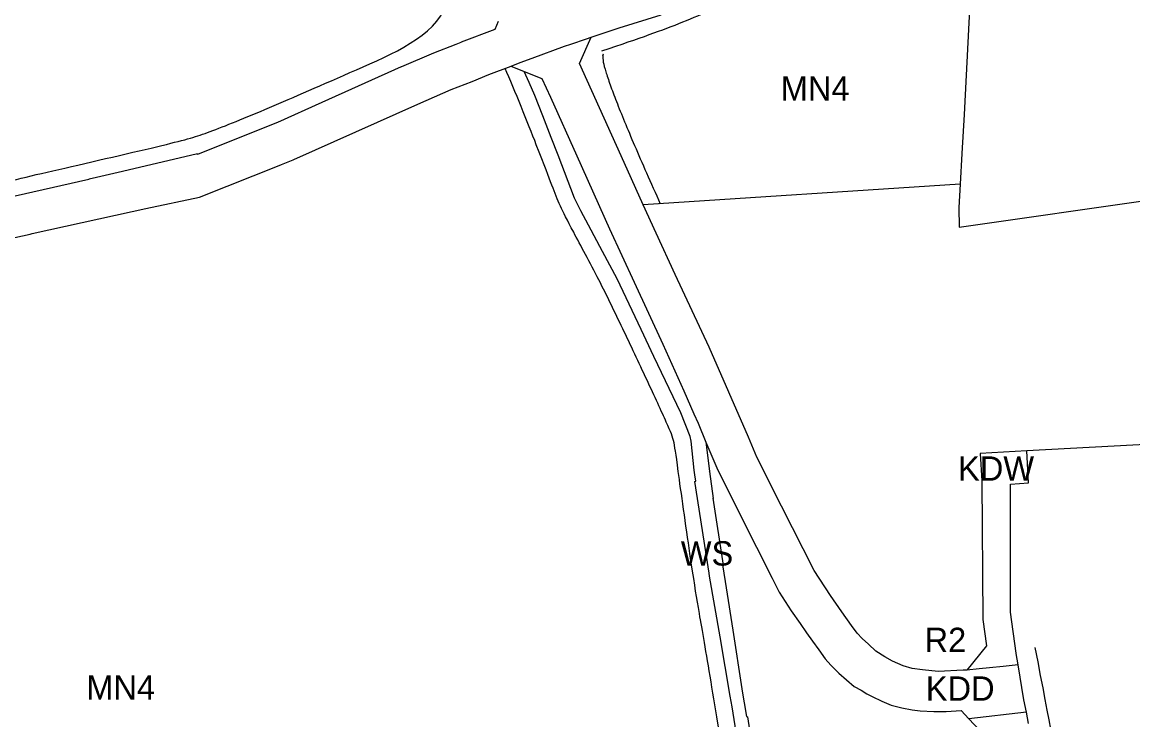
# Model space of a CAD drawing. Extents: x 7413438 to 7416393, y 5541665 to 5544118.
# Drawn here: x 7415261.6 to 7415535.1, y 5542643.7 to 5542815.6 of the extents above; entities that cross this region are included whole.
import ezdxf

# ---------------------------------------------------------------- set-up
doc = ezdxf.new("R2010")
doc.units = 0
for name, color, linetype in [('linie_rozgraniczajace', 7, 'Continuous'), ('linie_zabudowy_nieprzekraczalne', 7, 'Continuous'), ('oznaczenia_przeznaczen', 7, 'Continuous')]:
    doc.layers.add(name, color=color, linetype=linetype)

msp = doc.modelspace()

# ---------------------------------------------------------------- linework, layer by layer
at = {"layer": 'linie_rozgraniczajace'}
for p, q in [((7415495.27, 5542825.28), (7415494.71, 5542815.37)), ((7415378.77, 5542815.75), (7415377.96, 5542813.77)), ((7415408.58, 5542814.17), (7415418.95, 5542817.4)), ((7415494.71, 5542815.37), (7415493.57, 5542792.82)), ((7415377.96, 5542813.77), (7415369.66, 5542810.61)), ((7415402.47, 5542812.13), (7415407.64, 5542813.88)), ((7415407.64, 5542813.88), (7415408.58, 5542814.17)), ((7415368.34, 5542810.08), (7415362.89, 5542807.96)), ((7415369.65, 5542810.59), (7415368.34, 5542810.08)), ((7415369.66, 5542810.61), (7415369.65, 5542810.59)), ((7415395.17, 5542809.66), (7415396.67, 5542810.17)), ((7415396.67, 5542810.17), (7415400.56, 5542811.49)), ((7415398.83, 5542805.37), (7415401.7, 5542811.87)), ((7415400.56, 5542811.49), (7415401.7, 5542811.87)), ((7415401.7, 5542811.87), (7415402.47, 5542812.13)), ((7415362.89, 5542807.96), (7415355.01, 5542804.56)), ((7415387.22, 5542806.71), (7415395.17, 5542809.66)), ((7415354.95, 5542804.53), (7415335.37, 5542795.76)), ((7415355.01, 5542804.56), (7415354.95, 5542804.53)), ((7415376.48, 5542802.71), (7415382, 5542804.76)), ((7415382, 5542804.76), (7415384.26, 5542805.6)), ((7415382, 5542804.76), (7415382.15, 5542804.68)), ((7415382.15, 5542804.68), (7415385.21, 5542803.45)), ((7415384.26, 5542805.6), (7415387.22, 5542806.71)), ((7415409.81, 5542780.98), (7415398.83, 5542805.37)), ((7415372.42, 5542800.93), (7415376.48, 5542802.71)), ((7415386.41, 5542800.74), (7415385.21, 5542803.45)), ((7415385.21, 5542803.45), (7415389.54, 5542801.72)), ((7415389.54, 5542801.72), (7415391.71, 5542797.07)), ((7415359.01, 5542795.39), (7415367.27, 5542798.96)), ((7415367.27, 5542798.96), (7415372.42, 5542800.93)), ((7415387.86, 5542797.46), (7415386.41, 5542800.74)), ((7415389.79, 5542792.48), (7415387.86, 5542797.46)), ((7415391.71, 5542797.07), (7415398.18, 5542782.61)), ((7415335.37, 5542795.76), (7415324.48, 5542790.88)), ((7415328.48, 5542781.72), (7415359.01, 5542795.39)), ((7415324.48, 5542790.88), (7415321.74, 5542789.78)), ((7415391.86, 5542787.17), (7415389.79, 5542792.48)), ((7415493.57, 5542792.82), (7415493.04, 5542783.18)), ((7415321.72, 5542789.78), (7415304.76, 5542782.98)), ((7415321.74, 5542789.78), (7415321.72, 5542789.78)), ((7415393.56, 5542782.79), (7415391.86, 5542787.17)), ((7415304.77, 5542783.09), (7415286.27, 5542778.81)), ((7415304.76, 5542782.98), (7415304.77, 5542783.09)), ((7415397.59, 5542772.16), (7415393.56, 5542782.79)), ((7415398.18, 5542782.61), (7415406.25, 5542764.63)), ((7415493.04, 5542783.18), (7415492.63, 5542775.63)), ((7415305.2, 5542772.44), (7415325.27, 5542780.43)), ((7415325.27, 5542780.43), (7415325.4, 5542780.48)), ((7415325.4, 5542780.48), (7415325.46, 5542780.5)), ((7415325.46, 5542780.5), (7415328.3, 5542781.64)), ((7415328.3, 5542781.64), (7415328.48, 5542781.72)), ((7415414.56, 5542770.54), (7415409.81, 5542780.98)), ((7415278.77, 5542777.08), (7415277.94, 5542776.9)), ((7415286.27, 5542778.81), (7415278.77, 5542777.08)), ((7415277.94, 5542776.84), (7415253.36, 5542771.27)), ((7415277.94, 5542776.9), (7415277.94, 5542776.84)), ((7415492.63, 5542775.63), (7415414.56, 5542770.54)), ((7415492.63, 5542775.63), (7415492.31, 5542769.92)), ((7415292.05, 5542769.67), (7415305.2, 5542772.44)), ((7415399.13, 5542769.04), (7415397.59, 5542772.16)), ((7415492.37, 5542765.07), (7415540.54, 5542771.92)), ((7415264.02, 5542763.46), (7415288.69, 5542768.93)), ((7415288.69, 5542768.93), (7415292.05, 5542769.67)), ((7415401.02, 5542765.54), (7415399.13, 5542769.04)), ((7415417.74, 5542763.56), (7415414.56, 5542770.54)), ((7415492.31, 5542769.92), (7415492.37, 5542765.07)), ((7415259.77, 5542762.49), (7415263.52, 5542763.31)), ((7415263.52, 5542763.31), (7415264.02, 5542763.46)), ((7415404.52, 5542759.03), (7415401.02, 5542765.54)), ((7415406.25, 5542764.63), (7415412.33, 5542751.52)), ((7415422.38, 5542753.43), (7415417.74, 5542763.56)), ((7415408.11, 5542752.36), (7415404.52, 5542759.03)), ((7415414.06, 5542739.81), (7415408.11, 5542752.36)), ((7415430.81, 5542735.46), (7415422.38, 5542753.43)), ((7415412.33, 5542751.52), (7415419.4, 5542736.23)), ((7415417.18, 5542733.18), (7415414.06, 5542739.81)), ((7415419.4, 5542736.23), (7415424.52, 5542724.72)), ((7415423.77, 5542719.33), (7415417.18, 5542733.18)), ((7415440.43, 5542713.32), (7415430.81, 5542735.46)), ((7415424.52, 5542724.72), (7415427.02, 5542719.06)), ((7415426.09, 5542713.51), (7415423.77, 5542719.33)), ((7415427.02, 5542719.06), (7415428.05, 5542716.73)), ((7415428.05, 5542716.73), (7415430, 5542712.06)), ((7415426.33, 5542712.36), (7415426.09, 5542713.51)), ((7415427.09, 5542705.16), (7415426.33, 5542712.36)), ((7415430, 5542712.06), (7415430, 5542712.05)), ((7415430, 5542712.05), (7415430.83, 5542704.91)), ((7415430, 5542712.05), (7415432.63, 5542705.76)), ((7415442.51, 5542708.34), (7415440.43, 5542713.32)), ((7415562.02, 5542712.79), (7415509.03, 5542709.91)), ((7415509.03, 5542709.91), (7415497.55, 5542709.29)), ((7415497.55, 5542709.29), (7415497.92, 5542702.53)), ((7415509.43, 5542702.09), (7415509.03, 5542709.91)), ((7415448.64, 5542696.29), (7415442.51, 5542708.34)), ((7415427.22, 5542704), (7415427.08, 5542705.18)), ((7415427.08, 5542705.18), (7415427.09, 5542705.16)), ((7415427.47, 5542702.48), (7415427.22, 5542704)), ((7415430.82, 5542704.91), (7415430.83, 5542704.83)), ((7415430.83, 5542704.91), (7415430.82, 5542704.91)), ((7415430.83, 5542704.83), (7415431.76, 5542698.18)), ((7415432.63, 5542705.76), (7415439.75, 5542691.56)), ((7415427.28, 5542702.36), (7415427.42, 5542702.44)), ((7415430.78, 5542679.83), (7415427.28, 5542702.36)), ((7415427.42, 5542702.44), (7415427.47, 5542702.48)), ((7415497.92, 5542702.53), (7415498.18, 5542668.34)), ((7415504.99, 5542683.22), (7415505, 5542701.69)), ((7415505, 5542701.69), (7415509.43, 5542702.09)), ((7415431.76, 5542698.18), (7415431.66, 5542698.31)), ((7415431.66, 5542698.31), (7415434.25, 5542681.73)), ((7415456.66, 5542680.42), (7415448.64, 5542696.29)), ((7415439.75, 5542691.56), (7415442.46, 5542686.21)), ((7415442.46, 5542686.21), (7415446.3, 5542678.56)), ((7415434.25, 5542681.73), (7415434.15, 5542681.39)), ((7415434.15, 5542681.39), (7415434.96, 5542676.19)), ((7415504.98, 5542670.21), (7415504.99, 5542683.22)), ((7415430.76, 5542679.76), (7415430.82, 5542679.79)), ((7415430.88, 5542679.09), (7415430.76, 5542679.76)), ((7415430.82, 5542679.79), (7415430.78, 5542679.83)), ((7415433.46, 5542664.08), (7415430.88, 5542679.09)), ((7415446.3, 5542678.56), (7415448.02, 5542675.08)), ((7415460.67, 5542674.26), (7415456.66, 5542680.42)), ((7415434.96, 5542676.19), (7415436.58, 5542665.75)), ((7415448.02, 5542675.08), (7415450.97, 5542670.48)), ((7415463.47, 5542670.29), (7415460.67, 5542674.26)), ((7415450.97, 5542670.48), (7415453.17, 5542667.38)), ((7415465.85, 5542666.93), (7415463.47, 5542670.29)), ((7415506.43, 5542660.05), (7415504.98, 5542670.21)), ((7415498.18, 5542668.34), (7415499.06, 5542661.9)), ((7415436.58, 5542665.75), (7415438.85, 5542651.25)), ((7415453.17, 5542667.38), (7415454.77, 5542665.08)), ((7415454.77, 5542665.08), (7415456.2, 5542663)), ((7415467.25, 5542665.04), (7415465.85, 5542666.93)), ((7415468.51, 5542663.71), (7415467.25, 5542665.04)), ((7415435.97, 5542649.52), (7415433.46, 5542664.08)), ((7415456.2, 5542663), (7415457.81, 5542660.89)), ((7415470.07, 5542662.33), (7415468.51, 5542663.71)), ((7415471.86, 5542660.56), (7415470.07, 5542662.33)), ((7415457.81, 5542660.89), (7415459.34, 5542658.66)), ((7415474.05, 5542659.21), (7415471.86, 5542660.56)), ((7415499.06, 5542661.9), (7415494.26, 5542655.93)), ((7415506.38, 5542660.03), (7415506.43, 5542660.05)), ((7415506.87, 5542657.17), (7415506.38, 5542660.03)), ((7415459.34, 5542658.66), (7415460.74, 5542657.15)), ((7415460.74, 5542657.15), (7415462.74, 5542655.19)), ((7415475.93, 5542658.14), (7415474.05, 5542659.21)), ((7415478.57, 5542656.98), (7415475.93, 5542658.14)), ((7415480.78, 5542656.27), (7415478.57, 5542656.98)), ((7415503.19, 5542656.83), (7415499.8, 5542656.46)), ((7415506.87, 5542657.17), (7415503.19, 5542656.83)), ((7415508.33, 5542648.58), (7415506.87, 5542657.17)), ((7415462.74, 5542655.19), (7415464.63, 5542653.51)), ((7415483.32, 5542655.97), (7415480.78, 5542656.27)), ((7415487.15, 5542655.57), (7415483.32, 5542655.97)), ((7415493.34, 5542655.86), (7415487.15, 5542655.57)), ((7415494.26, 5542655.93), (7415493.34, 5542655.86)), ((7415497.29, 5542656.19), (7415494.26, 5542655.93)), ((7415499.8, 5542656.46), (7415497.29, 5542656.19)), ((7415438.85, 5542651.25), (7415438.84, 5542651.24)), ((7415438.84, 5542651.24), (7415439.99, 5542644.48)), ((7415464.63, 5542653.51), (7415466.48, 5542651.89)), ((7415466.48, 5542651.89), (7415468.21, 5542650.97)), ((7415435.95, 5542649.51), (7415435.97, 5542649.52)), ((7415436.45, 5542646.82), (7415435.95, 5542649.51)), ((7415468.21, 5542650.97), (7415469.62, 5542650.04)), ((7415469.62, 5542650.04), (7415470.96, 5542649.42)), ((7415470.96, 5542649.42), (7415473.34, 5542648.21)), ((7415508.93, 5542645.54), (7415508.33, 5542648.58)), ((7415439.82, 5542625.47), (7415436.45, 5542646.82)), ((7415473.34, 5542648.21), (7415475.58, 5542647.28)), ((7415475.58, 5542647.28), (7415478.23, 5542646.58)), ((7415478.23, 5542646.58), (7415480.8, 5542646.15)), ((7415480.8, 5542646.15), (7415482.79, 5542645.88)), ((7415482.79, 5542645.88), (7415486.15, 5542645.72)), ((7415486.15, 5542645.72), (7415489.12, 5542645.72)), ((7415489.12, 5542645.72), (7415492.85, 5542645.95)), ((7415492.85, 5542645.95), (7415494.75, 5542643.93)), ((7415439.99, 5542644.48), (7415440.19, 5542644.36)), ((7415440.19, 5542644.36), (7415442.67, 5542628.8)), ((7415508.93, 5542645.54), (7415494.75, 5542643.93)), ((7415494.75, 5542643.93), (7415500.11, 5542638.22)), ((7415509.47, 5542642.77), (7415508.93, 5542645.54))]:
    msp.add_line(p, q, dxfattribs=at)
at = {"layer": 'linie_zabudowy_nieprzekraczalne'}
for points, degree in [([(7415224.24, 5542764.93), (7415234.87, 5542768.93), (7415252.45, 5542775.15), (7415267.62, 5542778.59), (7415300.4, 5542786.16), (7415306.31, 5542787.89), (7415321.64, 5542794.04), (7415341.99, 5542803.09), (7415373.83, 5542816.66), (7415358.63, 5542848.96), (7415349.07, 5542869.68), (7415324.44, 5542923.07), (7415321.98, 5542928.69), (7415321.86, 5542932.66), (7415323.07, 5542937.93), (7415326.67, 5542952.06), (7415325.97, 5542960.66), (7415326.79, 5542972.64), (7415328.33, 5542984.95), (7415330.18, 5542999.75), (7415333.24, 5543013.48), (7415339.07, 5543034.4), (7415348.26, 5543068.35), (7415353.84, 5543088.85), (7415355.35, 5543096.84)], 3), ([(7415467.94, 5542842.69), (7415467.54, 5542841.13), (7415466.64, 5542839.86), (7415463.04, 5542837.46), (7415454.77, 5542832.15), (7415443.68, 5542825.04), (7415438.79, 5542821.9), (7415424.47, 5542815.43), (7415413.85, 5542811.6), (7415404.29, 5542808.46)], 3), ([(7415404.68, 5542807.68), (7415403.19, 5542805.36), (7415418.75, 5542770.79)], 2), ([(7415446.6, 5542629.27), (7415452.04, 5542595.33), (7415456.18, 5542568.61), (7415456.15, 5542564.66), (7415454.36, 5542562.27), (7415452.69, 5542561.56), (7415446.89, 5542562.18), (7415445, 5542563.92), (7415444.43, 5542566.07), (7415441.46, 5542584.43), (7415439.41, 5542597.71), (7415435.8, 5542621.33), (7415435.43, 5542627.48), (7415430.97, 5542654.89), (7415428.14, 5542671.28), (7415426.81, 5542679.05), (7415422.91, 5542706.51), (7415422.23, 5542712.31), (7415420.9, 5542715.65), (7415415.52, 5542727.29), (7415409.38, 5542740.3), (7415403.87, 5542751.75), (7415396.65, 5542765.15), (7415393.99, 5542770.37), (7415392.24, 5542774.92), (7415389.31, 5542782.59), (7415382.93, 5542798.83), (7415380.52, 5542804.19)], 3), ([(7415060.2, 5542700.03), (7415063.8, 5542694.82), (7415069.96, 5542687.2), (7415074.97, 5542682.48), (7415094.07, 5542670.45), (7415095.67, 5542670.19), (7415115.82, 5542663.31), (7415160.33, 5542649.35), (7415173.61, 5542643.76), (7415176.31, 5542642.11), (7415190.15, 5542632.51), (7415210.39, 5542618.3), (7415230.16, 5542603.31), (7415243.83, 5542592.3), (7415246.54, 5542589.46), (7415257.35, 5542580.95), (7415265.92, 5542574.94), (7415271.31, 5542571.58), (7415279.78, 5542563.89), (7415291.54, 5542557.48)], 3), ([(7415511.02, 5542661.49), (7415514.82, 5542641.66), (7415518.03, 5542625.4), (7415520.38, 5542613.91), (7415521.88, 5542606.92), (7415522.86, 5542602.65), (7415523.63, 5542599.54), (7415524.21, 5542597.31), (7415524.55, 5542596.01), (7415524.69, 5542595.48), (7415524.73, 5542595.33), (7415524.75, 5542595.24), (7415524.77, 5542595.12), (7415524.79, 5542595.01), (7415524.84, 5542594.68), (7415524.96, 5542593.68), (7415525.22, 5542591.69), (7415525.51, 5542589.37), (7415525.72, 5542587.69), (7415525.81, 5542587), (7415525.83, 5542586.86), (7415525.85, 5542586.73), (7415525.95, 5542586), (7415526.22, 5542584), (7415526.69, 5542580.57), (7415527.28, 5542576.2), (7415527.92, 5542571.51), (7415528.49, 5542567.31), (7415528.88, 5542564.47), (7415529.12, 5542562.61), (7415529.54, 5542559.36), (7415530.37, 5542552.75), (7415531.4, 5542544.63), (7415532.19, 5542538.42), (7415532.57, 5542535.35), (7415532.87, 5542532.85), (7415533.39, 5542528.45), (7415534.03, 5542522.94), (7415534.53, 5542518.68), (7415534.74, 5542516.81), (7415534.79, 5542516.39), (7415534.8, 5542516.31), (7415534.81, 5542516.2), (7415534.81, 5542516.09), (7415534.82, 5542515.91), (7415534.82, 5542515.42), (7415534.82, 5542514.39), (7415534.82, 5542513.09), (7415534.82, 5542512.04), (7415534.82, 5542511.55), (7415534.81, 5542511.38), (7415534.81, 5542511.28), (7415534.8, 5542511.17), (7415534.79, 5542511.06), (7415534.72, 5542510.45), (7415534.35, 5542507.63), (7415533.49, 5542500.98), (7415532.47, 5542491.97), (7415531.63, 5542477.4), (7415559.07, 5542470.57), (7415584.68, 5542465.35), (7415619.26, 5542458.32), (7415619.26, 5542458.32), (7415651.48, 5542451.74), (7415651.6, 5542451.72), (7415651.67, 5542451.7), (7415702.44, 5542439.32), (7415707.66, 5542438.37), (7415707.77, 5542438.33), (7415727.6, 5542432.09), (7415757.24, 5542424.08), (7415775.01, 5542419.29), (7415812.56, 5542410.29), (7415812.58, 5542410.29), (7415831.04, 5542405.78), (7415848.22, 5542401.59), (7415877.11, 5542394.69), (7415893.94, 5542390.97), (7415909.41, 5542389.1), (7415919.17, 5542387.92), (7415919.38, 5542387.89), (7415950.44, 5542383.02)], 3)]:
    msp.add_open_spline(points, degree=degree, dxfattribs=at)

# ---------------------------------------------------------------- texts
at = {"layer": 'oznaczenia_przeznaczen'}
for s, p in [('MN4', (7415448.42, 5542796.23)), ('KDW', (7415492.1, 5542702.58)), ('WS', (7415423.79, 5542681.67)), ('R2', (7415483.84, 5542660.35)), ('MN4', (7415277.36, 5542648.64)), ('KDD', (7415484.15, 5542648.36))]:
    msp.add_text(s, height=6, dxfattribs=at).set_placement(p)

doc.saveas('drawing.dxf')
